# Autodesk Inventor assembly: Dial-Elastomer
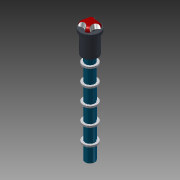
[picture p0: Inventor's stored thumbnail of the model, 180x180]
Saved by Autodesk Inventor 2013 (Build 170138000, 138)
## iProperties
Shininess: 64.0
Length Units: 11272
Angle Units: 11279
Time Units: 11290
Mass Units: 11286
Length Display Precision: 3
Angle Display Precision: 2
Compacted: True
Created: 2001-11
Part Number: Dial-Elastomer
Document SubType Name: Assembly
Designer: Autodesk, Inc.
Mass: 34.1122 g
Surface Area: 233.654 cm^2
Volume: 34.1122 cm^3
Density: 1 g/cm^3
Density: 0.0
Volumn: 0.0
Area: 0.0
PropertySet Name: Model Information
Control State: 0
Master: False
Checked Out: False
Author: Autodesk, Inc.
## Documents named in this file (7)
- C:\Users\boganb\Documents\B2 Design\Goodyear\2013 Tutorial Files\Assembly FEA 3\Components\Dial-Elastomer.iam
- C:\Users\boganb\Documents\B2 Design\Goodyear\2013 Tutorial Files\Assembly FEA 3\Components\Dial-cap.ipt
- C:\Users\boganb\Documents\B2 Design\Goodyear\2013 Tutorial Files\Assembly FEA 3\Components\Dial-Cover.ipt
- C:\Users\boganb\Documents\B2 Design\Goodyear\2013 Tutorial Files\Assembly FEA 3\Components\Dial.ipt
- C:\Users\boganb\Documents\B2 Design\Goodyear\2013 Tutorial Files\Assembly FEA 3\Components\Elastomer.ipt
- C:\Users\boganb\Documents\B2 Design\Goodyear\2013 Tutorial Files\Assembly FEA 3\Components\Spacer.ipt
- C:\Users\boganb\Documents\B2 Design\Goodyear\2013 Tutorial Files\Assembly FEA 3\Components\Dial-Base.ipt
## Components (15 placed, 6 different names)
1. PART1_1 — Insert:14, Mate:1, Mate:2, Mate:3
2. Elastomer:1 — Insert:3, Insert:16
3. Dial-Cap — Insert:1, Insert:14
4. Dial-Base:1 — Mate:1, Mate:2, Insert:15, Insert:16
5. Dial:2 — Insert:1, Insert:15
6. Spacer:7 — Insert:3, Insert:5
7. Spacer:8 — Insert:12, Insert:13
8. Elastomer:6 — Insert:5, Insert:6
9. Elastomer:7 — Insert:11, Insert:12
10. Elastomer:8 — Insert:9, Insert:10
11. Elastomer:9 — Insert:7, Insert:8
12. Spacer:9 — Insert:10, Insert:11
13. Spacer:10 — Insert:8, Insert:9
14. Spacer:11 — Insert:6, Insert:7
15. Elastomer:10 — Insert:13
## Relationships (17: Insert 14, Mate 3)
- Insert:1: Dial-Cap ↔ Dial:2
- Insert:3: Elastomer:1 ↔ Spacer:7
- Insert:5: Spacer:7 ↔ Elastomer:6
- Insert:6: Elastomer:6 ↔ Spacer:11
- Insert:7: Elastomer:9 ↔ Spacer:11
- Insert:8: Elastomer:9 ↔ Spacer:10
- Insert:9: Elastomer:8 ↔ Spacer:10
- Insert:10: Elastomer:8 ↔ Spacer:9
- Insert:11: Elastomer:7 ↔ Spacer:9
- Insert:12: Spacer:8 ↔ Elastomer:7
- Insert:13: Spacer:8 ↔ Elastomer:10
- Insert:14: PART1_1 ↔ Dial-Cap
- Mate:1: PART1_1 ↔ Dial-Base:1
- Mate:2: PART1_1 ↔ Dial-Base:1
- Insert:15: Dial-Base:1 ↔ Dial:2
- Insert:16: Elastomer:1 ↔ Dial-Base:1
- Mate:3: PART1_1
